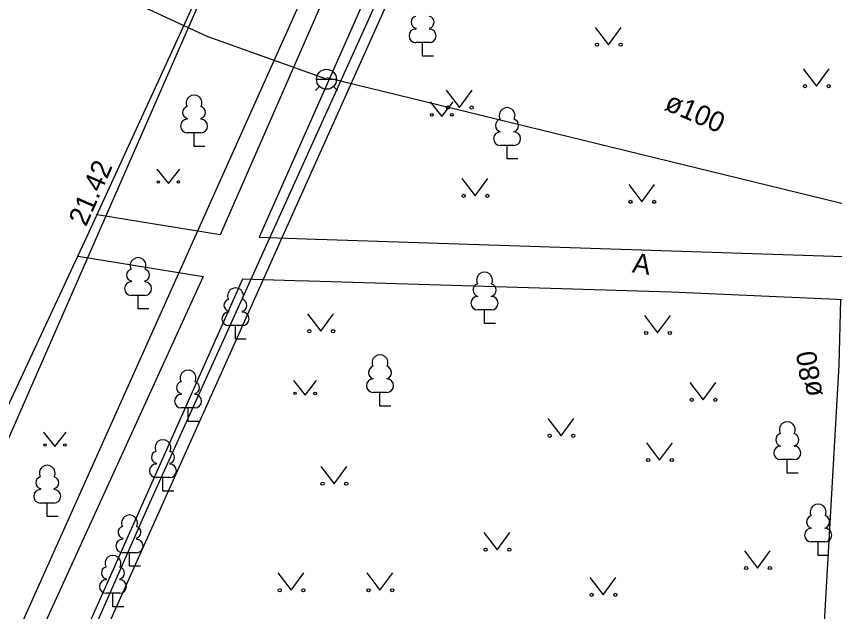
# Model space of a CAD drawing. Extents: x 714391 to 714584, y 6589993 to 6590151.
# Drawn here: x 714428.09 to 714456.74, y 6590031.55 to 6590052.39 of the extents above; entities that cross this region are included whole.
import ezdxf

# ---------------------------------------------------------------- set-up
doc = ezdxf.new("R2010")
doc.units = 0
for name, color, linetype in [('HALJASTUS', 7, 'Continuous'), ('HOONE', 7, 'Continuous'), ('KORGUS', 7, 'Continuous'), ('KPKAABEL', 7, 'Continuous'), ('PUU', 7, 'Continuous'), ('SKTRASS', 7, 'Continuous'), ('TEE', 7, 'Continuous'), ('TORU NR', 7, 'Continuous'), ('VKAEV', 7, 'Continuous'), ('VTRASS', 7, 'Continuous'), ('Слой 1', 7, 'Continuous')]:
    doc.layers.add(name, color=color, linetype=linetype)

msp = doc.modelspace()

# ---------------------------------------------------------------- linework, layer by layer
at = {"layer": 'HALJASTUS'}
for p, q in [((714448.357, 6590052.007), (714448.82, 6590051.4)), ((714448.82, 6590051.4), (714449.266, 6590052.007)), ((714455.637, 6590050.557), (714456.1, 6590049.95)), ((714456.1, 6590049.95), (714456.546, 6590050.557)), ((714443.137, 6590049.807), (714443.6, 6590049.2)), ((714443.6, 6590049.2), (714444.046, 6590049.807)), ((714442.582, 6590049.395), (714442.987, 6590048.89)), ((714442.987, 6590048.89), (714443.382, 6590049.395)), ((714433.009, 6590047.047), (714433.414, 6590046.542)), ((714433.414, 6590046.542), (714433.809, 6590047.047)), ((714443.687, 6590046.717), (714444.15, 6590046.11)), ((714444.15, 6590046.11), (714444.596, 6590046.717)), ((714449.527, 6590046.507), (714449.99, 6590045.9)), ((714449.99, 6590045.9), (714450.436, 6590046.507)), ((714438.287, 6590041.977), (714438.75, 6590041.37)), ((714438.75, 6590041.37), (714439.196, 6590041.977)), ((714450.077, 6590041.917), (714450.54, 6590041.31)), ((714450.54, 6590041.31), (714450.986, 6590041.917)), ((714437.795, 6590039.642), (714438.2, 6590039.137)), ((714438.2, 6590039.137), (714438.595, 6590039.642)), ((714451.667, 6590039.577), (714452.13, 6590038.97)), ((714452.13, 6590038.97), (714452.576, 6590039.577)), ((714446.697, 6590038.317), (714447.16, 6590037.71)), ((714447.16, 6590037.71), (714447.606, 6590038.317)), ((714429.036, 6590037.835), (714429.441, 6590037.33)), ((714429.441, 6590037.33), (714429.836, 6590037.835)), ((714450.147, 6590037.467), (714450.61, 6590036.86)), ((714450.61, 6590036.86), (714451.056, 6590037.467)), ((714438.747, 6590036.637), (714439.21, 6590036.03)), ((714439.21, 6590036.03), (714439.656, 6590036.637)), ((714444.457, 6590034.327), (714444.92, 6590033.72)), ((714444.92, 6590033.72), (714445.366, 6590034.327)), ((714453.577, 6590033.687), (714454.04, 6590033.08)), ((714454.04, 6590033.08), (714454.486, 6590033.687)), ((714437.247, 6590032.907), (714437.71, 6590032.3)), ((714437.71, 6590032.3), (714438.156, 6590032.907)), ((714440.357, 6590032.907), (714440.82, 6590032.3)), ((714440.82, 6590032.3), (714441.266, 6590032.907)), ((714448.167, 6590032.747), (714448.63, 6590032.14)), ((714448.63, 6590032.14), (714449.076, 6590032.747))]:
    msp.add_line(p, q, dxfattribs=at)
for centre, radius in [((714448.419, 6590051.4), 0.055), ((714449.248, 6590051.4), 0.055), ((714455.699, 6590049.95), 0.055), ((714456.528, 6590049.95), 0.055), ((714443.199, 6590049.2), 0.055), ((714444.028, 6590049.2), 0.055), ((714442.634, 6590048.945), 0.0428), ((714443.334, 6590048.945), 0.0452), ((714433.061, 6590046.597), 0.0428), ((714433.761, 6590046.597), 0.0452), ((714443.749, 6590046.11), 0.055), ((714444.578, 6590046.11), 0.055), ((714449.589, 6590045.9), 0.055), ((714450.418, 6590045.9), 0.055), ((714438.349, 6590041.37), 0.055), ((714439.178, 6590041.37), 0.055), ((714450.139, 6590041.31), 0.055), ((714450.968, 6590041.31), 0.055), ((714437.847, 6590039.192), 0.0428), ((714438.547, 6590039.192), 0.0452), ((714451.729, 6590038.97), 0.055), ((714452.558, 6590038.97), 0.055), ((714446.759, 6590037.71), 0.055), ((714447.588, 6590037.71), 0.055), ((714429.088, 6590037.386), 0.0428), ((714429.788, 6590037.386), 0.0452), ((714450.209, 6590036.86), 0.055), ((714451.038, 6590036.86), 0.055), ((714438.809, 6590036.03), 0.055), ((714439.638, 6590036.03), 0.055), ((714444.519, 6590033.72), 0.055), ((714445.348, 6590033.72), 0.055), ((714453.639, 6590033.08), 0.055), ((714454.468, 6590033.08), 0.055), ((714437.309, 6590032.3), 0.055), ((714438.138, 6590032.3), 0.055), ((714440.419, 6590032.3), 0.055), ((714441.248, 6590032.3), 0.055), ((714448.229, 6590032.14), 0.055), ((714449.058, 6590032.14), 0.055)]:
    msp.add_circle(centre, radius, dxfattribs=at)
at = {"layer": 'HOONE'}
for points in [[(714459.73, 6590096.05), (714450.33, 6590074.44), (714440.46, 6590052.39), (714432.7, 6590035.24), (714421.56, 6590009.98), (714417.1, 6590000.12), (714413.783, 6589992.711)], [(714458.89, 6590022.24), (714455.84, 6590022.32), (714456.07, 6590025.65), (714456.9, 6590040.18), (714456.96, 6590042.47)]]:
    msp.add_lwpolyline(points, dxfattribs=at)
at = {"layer": 'KPKAABEL'}
msp.add_lwpolyline([(714390.649, 6590090.709), (714391.22, 6590087.72), (714411.651, 6590078.699), (714417.543, 6590076.021), (714419.18, 6590075.27), (714445.64, 6590069.88), (714433.16, 6590042.04), (714420.76, 6590014.4), (714410.92, 6589992.711)], dxfattribs=at)
at = {"layer": 'PUU'}
for p, q in [((714442.07, 6590051.98), (714442.07, 6590051.95)), ((714442.55, 6590051.98), (714442.55, 6590051.95)), ((714442.55, 6590051.98), (714442.55, 6590051.95)), ((714442.55, 6590051.475), (714442.07, 6590051.475)), ((714442.55, 6590051.475), (714442.07, 6590051.475)), ((714442.31, 6590051), (714442.31, 6590051.475)), ((714442.31, 6590051), (714442.31, 6590051.475)), ((714442.69, 6590051), (714442.31, 6590051)), ((714442.69, 6590051), (714442.31, 6590051)), ((714434.07, 6590048.82), (714434.07, 6590048.79)), ((714434.55, 6590048.82), (714434.55, 6590048.79)), ((714434.55, 6590048.315), (714434.07, 6590048.315)), ((714434.31, 6590047.84), (714434.31, 6590048.315)), ((714445.51, 6590047.875), (714445.03, 6590047.875)), ((714445.27, 6590047.4), (714445.27, 6590047.875)), ((714434.69, 6590047.84), (714434.31, 6590047.84)), ((714445.65, 6590047.4), (714445.27, 6590047.4)), ((714432.11, 6590043.13), (714432.11, 6590043.1)), ((714432.59, 6590043.13), (714432.59, 6590043.1)), ((714432.59, 6590042.625), (714432.11, 6590042.625)), ((714432.35, 6590042.15), (714432.35, 6590042.625)), ((714432.73, 6590042.15), (714432.35, 6590042.15)), ((714435.52, 6590042.07), (714435.52, 6590042.04)), ((714436, 6590042.07), (714436, 6590042.04)), ((714444.72, 6590042.115), (714444.24, 6590042.115)), ((714444.48, 6590041.64), (714444.48, 6590042.115)), ((714436, 6590041.565), (714435.52, 6590041.565)), ((714435.76, 6590041.09), (714435.76, 6590041.565)), ((714444.86, 6590041.64), (714444.48, 6590041.64)), ((714436.14, 6590041.09), (714435.76, 6590041.09)), ((714433.86, 6590039.19), (714433.86, 6590039.16)), ((714434.34, 6590039.19), (714434.34, 6590039.16)), ((714441.06, 6590039.225), (714440.58, 6590039.225)), ((714440.82, 6590038.75), (714440.82, 6590039.225)), ((714441.2, 6590038.75), (714440.82, 6590038.75)), ((714434.34, 6590038.685), (714433.86, 6590038.685)), ((714434.1, 6590038.21), (714434.1, 6590038.685)), ((714434.48, 6590038.21), (714434.1, 6590038.21)), ((714432.98, 6590036.75), (714432.98, 6590036.72)), ((714433.46, 6590036.75), (714433.46, 6590036.72)), ((714455.32, 6590036.875), (714454.84, 6590036.875)), ((714455.08, 6590036.4), (714455.08, 6590036.875)), ((714455.46, 6590036.4), (714455.08, 6590036.4)), ((714433.46, 6590036.245), (714432.98, 6590036.245)), ((714433.22, 6590035.77), (714433.22, 6590036.245)), ((714428.93, 6590035.86), (714428.93, 6590035.83)), ((714429.41, 6590035.86), (714429.41, 6590035.83)), ((714433.6, 6590035.77), (714433.22, 6590035.77)), ((714429.41, 6590035.355), (714428.93, 6590035.355)), ((714429.17, 6590034.88), (714429.17, 6590035.355)), ((714429.55, 6590034.88), (714429.17, 6590034.88)), ((714431.81, 6590034.12), (714431.81, 6590034.09)), ((714432.29, 6590034.12), (714432.29, 6590034.09)), ((714456.4, 6590033.995), (714455.92, 6590033.995)), ((714456.16, 6590033.52), (714456.16, 6590033.995)), ((714432.29, 6590033.615), (714431.81, 6590033.615)), ((714432.05, 6590033.14), (714432.05, 6590033.615)), ((714456.54, 6590033.52), (714456.16, 6590033.52)), ((714432.43, 6590033.14), (714432.05, 6590033.14)), ((714431.23, 6590032.7), (714431.23, 6590032.67)), ((714431.71, 6590032.7), (714431.71, 6590032.67)), ((714431.71, 6590032.195), (714431.23, 6590032.195)), ((714431.47, 6590031.72), (714431.47, 6590032.195)), ((714431.85, 6590031.72), (714431.47, 6590031.72))]:
    msp.add_line(p, q, dxfattribs=at)
for centre, radius, start, end in [((714442.12, 6590052.188), 0.212, 105.2441, 257.079), ((714442.5, 6590052.188), 0.212, 282.921, 74.7559), ((714442.5, 6590052.188), 0.212, 282.921, 74.7559), ((714442.073, 6590051.713), 0.237, 90, 270), ((714442.547, 6590051.713), 0.237, 270, 90), ((714442.547, 6590051.713), 0.237, 270, 90), ((714442.073, 6590051.713), 0.237, 250.6828, 270), ((714434.31, 6590049.36), 0.277, 332.5799, 207.4201), ((714434.12, 6590049.027), 0.212, 105.2441, 257.079), ((714434.5, 6590049.027), 0.212, 282.921, 74.7559), ((714445.27, 6590048.92), 0.277, 332.5799, 207.4201), ((714434.073, 6590048.553), 0.237, 90, 270), ((714434.547, 6590048.553), 0.237, 270, 90), ((714445.1, 6590048.573), 0.233, 109.0217, 253.1415), ((714445.44, 6590048.573), 0.233, 286.8508, 70.9859), ((714445.033, 6590048.112), 0.238, 90.0016, 269.3953), ((714445.507, 6590048.112), 0.238, 270.6047, 89.9984), ((714432.35, 6590043.67), 0.277, 332.5799, 207.4201), ((714432.16, 6590043.338), 0.212, 105.2441, 257.079), ((714432.54, 6590043.338), 0.212, 282.921, 74.7559), ((714444.48, 6590043.16), 0.277, 332.5799, 207.4201), ((714432.112, 6590042.862), 0.237, 90, 270), ((714432.587, 6590042.862), 0.237, 270, 90), ((714444.31, 6590042.813), 0.233, 109.0217, 253.1415), ((714444.65, 6590042.813), 0.233, 286.8508, 70.9859), ((714435.76, 6590042.61), 0.277, 332.5799, 207.4201), ((714435.57, 6590042.277), 0.212, 105.2441, 257.079), ((714435.95, 6590042.277), 0.212, 282.921, 74.7559), ((714444.243, 6590042.352), 0.238, 90.0016, 269.3953), ((714444.717, 6590042.352), 0.238, 270.6047, 89.9984), ((714435.522, 6590041.803), 0.237, 90, 270), ((714435.997, 6590041.803), 0.237, 270, 90), ((714440.82, 6590040.27), 0.277, 332.5799, 207.4201), ((714440.65, 6590039.923), 0.233, 109.0217, 253.1415), ((714440.99, 6590039.923), 0.233, 286.8508, 70.9859), ((714434.1, 6590039.73), 0.277, 332.5799, 207.4201), ((714433.91, 6590039.397), 0.212, 105.2441, 257.079), ((714434.29, 6590039.397), 0.212, 282.921, 74.7559), ((714440.583, 6590039.462), 0.238, 90.0016, 269.3953), ((714441.057, 6590039.462), 0.238, 270.6047, 89.9984), ((714433.862, 6590038.923), 0.237, 90, 270), ((714434.337, 6590038.923), 0.237, 270, 90), ((714455.08, 6590037.92), 0.277, 332.5799, 207.4201), ((714433.22, 6590037.29), 0.277, 332.5799, 207.4201), ((714454.91, 6590037.573), 0.233, 109.0217, 253.1415), ((714455.25, 6590037.573), 0.233, 286.8508, 70.9859), ((714454.843, 6590037.112), 0.238, 90.0016, 269.3953), ((714455.317, 6590037.112), 0.238, 270.6047, 89.9984), ((714433.03, 6590036.958), 0.212, 105.2441, 257.079), ((714433.41, 6590036.958), 0.212, 282.921, 74.7559), ((714432.983, 6590036.483), 0.237, 90, 270), ((714433.458, 6590036.483), 0.237, 270, 90), ((714429.17, 6590036.4), 0.277, 332.5799, 207.4201), ((714428.98, 6590036.067), 0.212, 105.2441, 257.079), ((714429.36, 6590036.067), 0.212, 282.921, 74.7559), ((714428.932, 6590035.593), 0.237, 90, 270), ((714429.407, 6590035.593), 0.237, 270, 90), ((714456.16, 6590035.04), 0.277, 332.5799, 207.4201), ((714432.05, 6590034.66), 0.277, 332.5799, 207.4201), ((714455.99, 6590034.693), 0.233, 109.0217, 253.1415), ((714456.33, 6590034.693), 0.233, 286.8508, 70.9859), ((714431.86, 6590034.328), 0.212, 105.2441, 257.079), ((714432.24, 6590034.328), 0.212, 282.921, 74.7559), ((714455.923, 6590034.232), 0.238, 90.0016, 269.3953), ((714456.397, 6590034.232), 0.238, 270.6047, 89.9984), ((714431.812, 6590033.853), 0.237, 90, 270), ((714432.287, 6590033.853), 0.237, 270, 90), ((714431.47, 6590033.24), 0.277, 332.5799, 207.4201), ((714431.28, 6590032.908), 0.212, 105.2441, 257.079), ((714431.66, 6590032.908), 0.212, 282.921, 74.7559), ((714431.233, 6590032.433), 0.237, 90, 270), ((714431.708, 6590032.433), 0.237, 270, 90)]:
    msp.add_arc(centre, radius, start, end, dxfattribs=at)
at = {"layer": 'SKTRASS'}
msp.add_line((714437.189, 6590059.042), (714419.801, 6590019.338), dxfattribs=at)
at = {"layer": 'TEE'}
for points in [[(714439.555, 6590064.499), (714443.68, 6590064.07), (714435.23, 6590044.74), (714430.917, 6590045.447)], [(714459.31, 6590061.9), (714458.22, 6590062.47), (714447.303, 6590063.601), (714447.271, 6590063.604), (714445.09, 6590063.83), (714436.59, 6590044.66), (714438.563, 6590044.596), (714438.967, 6590044.582), (714457.41, 6590043.98), (714457.72, 6590044.12), (714458.5, 6590044.49)], [(714406.684, 6589992.711), (714411.807, 6590003.978), (714420.103, 6590022.258), (714430.572, 6590044.696), (714436.708, 6590058.068)], [(714430.249, 6590044.003), (714434.63, 6590043.29), (714427.02, 6590026.64), (714422.304, 6590026.966)], [(714458.41, 6590041.84), (714457.61, 6590042.45), (714451.01, 6590042.74), (714438.326, 6590043.121), (714437.835, 6590043.135), (714436.01, 6590043.19), (714428.72, 6590026.84), (714430.208, 6590026.691), (714430.977, 6590026.614), (714435.5, 6590026.16), (714448.72, 6590024.98), (714455.07, 6590024.44), (714457.48, 6590024.27)]]:
    msp.add_lwpolyline(points, dxfattribs=at)
at = {"layer": 'VKAEV'}
for p, q in [((714438.598, 6590050.19), (714439.298, 6590050.19)), ((714438.701, 6590049.943), (714438.561, 6590049.803)), ((714439.195, 6590049.943), (714439.335, 6590049.803))]:
    msp.add_line(p, q, dxfattribs=at)
msp.add_circle((714438.948, 6590050.19), 0.35, dxfattribs=at)
at = {"layer": 'VTRASS'}
msp.add_line((714438.963, 6590050.251), (714460.04, 6590045.1), dxfattribs=at)
msp.add_lwpolyline([(714438.948, 6590050.19), (714434.765, 6590051.691), (714426.564, 6590055.491), (714421.748, 6590057.766), (714420.884, 6590057.818)], dxfattribs=at)
at = {"layer": 'Слой 1'}
msp.add_lwpolyline([(714455.78, 6590085.63), (714478.99, 6590085.97), (714478.28, 6590068.22), (714475.39, 6590009.54), (714423.1, 6590012.8)], close=True, dxfattribs=at)

# ---------------------------------------------------------------- texts
at = {"layer": 'KORGUS'}
msp.add_text('21.42', height=0.7, rotation=66.3093, dxfattribs=at).set_placement((714430.528, 6590045.006))
at = {"layer": 'TEE'}
msp.add_text('A', height=0.7, rotation=351.2292, dxfattribs=at).set_placement((714449.626, 6590043.434))
at = {"layer": 'TORU NR'}
for s, rotation, p in [('ø100', 336.6493, (714450.739, 6590049.14)), ('ø80', 98.7005, (714456.316, 6590039.127))]:
    msp.add_text(s, height=0.7, rotation=rotation, dxfattribs=at).set_placement(p)

doc.saveas('drawing.dxf')
